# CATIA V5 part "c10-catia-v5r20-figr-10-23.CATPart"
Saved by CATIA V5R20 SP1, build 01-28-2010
Part number: Part1
Bounding box of the stored display mesh (mm): x -180.516 to 0, y -36.805 to 65.824, z 0 to 36.805
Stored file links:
  D:\v5_r20\psrt_files_downloaded\c10\c10-catia-v5r20-figr-10-23.CATPart
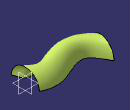
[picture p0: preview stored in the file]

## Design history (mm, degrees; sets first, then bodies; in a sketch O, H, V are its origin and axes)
Set1
  Sweep1: type Unspec, Profile Sketch2, Guide Sketch1
Body1 (main body)
  Sketch1 on xy-plane, origin (0, 0, 0), H (1, 0, 0), V (0, 1, 0)
    spline S1 through (0, 0) (-31.5913, 14.7273) (-94.8038, 0) (-174.5181, 29.5113)
    point P1 (0, 0)
    point P2 (-94.8038, 0)
    coincidence: P1 O, P2 H
  Sketch2 on yz-plane, origin (0, 0, 0), H (0, 1, 0), V (0, 0, 1)
    arc A1 centre (0, 0) radius 36.8048 from (36.8048, 0) to (-36.8048, 0) ccw
    point P1 (-36.8048, 0)
    point P2 (36.8048, 0)
    coincidence: P1 H, P2 H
